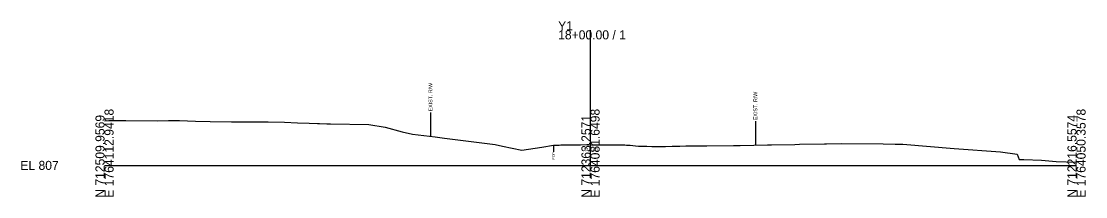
# Model space of a CAD drawing. Extents: x -26 to 1303, y -10 to 9524.
# Drawn here: x -25.7 to 302.8, y 7990.3 to 8044.6 of the extents above; entities that cross this region are included whole.
import ezdxf

# ---------------------------------------------------------------- set-up
doc = ezdxf.new("R2010")
doc.units = 0
for name, color, linetype in [('Default', 7, 'Continuous'), ('Exist Cross Section Cell', 7, 'Continuous'), ('Exist XS Center Line Elevation Label', 7, 'Continuous'), ('Exist XS Ground Line', 7, 'Continuous'), ('Old_Level_10', 7, 'Continuous')]:
    doc.layers.add(name, color=color, linetype=linetype)

msp = doc.modelspace()

# ---------------------------------------------------------------- linework, layer by layer
at = {"layer": 'Exist Cross Section Cell'}
for p, q in [((150, 8000), (150, 8041.75)), ((0, 8000), (150, 8000)), ((150, 8000), (300, 8000))]:
    msp.add_line(p, q, dxfattribs=at)
at = {"layer": 'Exist XS Ground Line'}
msp.add_lwpolyline([(0, 8013.77), (1.29, 8013.85), (2.56, 8013.9), (3.82, 8013.91), (4.25, 8013.89), (5.13, 8013.92), (6.6, 8013.92), (16.38, 8013.8), (19.71, 8013.85), (23.17, 8013.83), (28.09, 8013.65), (32.61, 8013.61), (39.14, 8013.49), (40.34, 8013.48), (42.57, 8013.45), (50.5, 8013.51), (55.51, 8013.38), (59.55, 8013.15), (63.21, 8013), (65.78, 8012.99), (66.33, 8012.97), (68.63, 8012.89), (69.71, 8012.81), (81.61, 8012.65), (86.6, 8011.86), (91.83, 8010.34), (95.03, 8009.69), (102.06, 8008.81), (104.98, 8008.41), (120.54, 8006.42), (122.87, 8005.99), (128.79, 8004.72), (134.95, 8005.63), (138.58, 8006.25), (139.29, 8006.28), (140.33, 8006.3), (140.85, 8006.31), (141.83, 8006.32), (143.6, 8006.33), (144.38, 8006.34), (145.71, 8006.37), (146.94, 8006.38), (148.84, 8006.41), (149.5, 8006.41), (150.35, 8006.39), (151.05, 8006.39), (152.05, 8006.39), (154.14, 8006.37), (154.61, 8006.37), (155.34, 8006.37), (157.16, 8006.36), (158.35, 8006.35), (159.72, 8006.34), (160.59, 8006.31), (161.1, 8006.3), (162.28, 8006.21), (163.9, 8006.06), (164.83, 8005.98), (166.78, 8005.92), (167.39, 8005.91), (168.88, 8005.86), (169.95, 8005.81), (170.99, 8005.82), (172.5, 8005.83), (173.1, 8005.84), (175.2, 8005.91), (175.88, 8005.93), (177.31, 8005.97), (177.61, 8005.98), (179.42, 8006.02), (180.17, 8006.02), (181.52, 8006.04), (182.73, 8006.04), (184.58, 8006.04), (185.28, 8006.04), (185.87, 8006.06), (194.09, 8006.16), (196.17, 8006.14), (204.6, 8006.36), (205.88, 8006.37), (213.02, 8006.49), (214.55, 8006.52), (222.18, 8006.66), (222.8, 8006.66), (227.57, 8006.79), (240.3, 8006.65), (244.01, 8006.57), (246.39, 8006.57), (262.24, 8005.24), (276.56, 8004.14), (281.7, 8003.51), (282.32, 8001.83), (283.7, 8001.78), (289.24, 8001.59), (293.73, 8001.2), (300, 8001.01)], dxfattribs=at)
at = {"layer": 'Old_Level_10'}
for p, q in [((100.6, 8016.4), (100.6, 8009)), ((200.87, 8013.66), (200.87, 8006.26)), ((138.58, 8006.25), (138.58, 8004.2))]:
    msp.add_line(p, q, dxfattribs=at)

# ---------------------------------------------------------------- texts
at = {"layer": 'Default'}
msp.add_text('-', height=0.0001, dxfattribs=at).set_placement((0, 8000))
at = {"layer": 'Exist Cross Section Cell'}
for s, p in [('Y1', (140, 8041.75)), ('18+00.00 / 1', (140, 8038.95)), ('EL 807', (-26, 7998.6))]:
    msp.add_text(s, height=2.8, dxfattribs=at).set_placement(p)
for s, p in [('E 1764112.9418', (2.8, 7990)), ('E 1764081.6498', (152.8, 7990)), ('E 1764050.3578', (302.8, 7990)), ('N 712509.9569', (0, 7990)), ('N 712363.2571', (150, 7990)), ('N 712216.5574', (300, 7990))]:
    msp.add_text(s, height=2.8, rotation=90, dxfattribs=at).set_placement(p)
at = {"layer": 'Exist XS Center Line Elevation Label'}
msp.add_text('813.40', height=1, dxfattribs=at).set_placement((147.97, 8004.4))
at = {"layer": 'Old_Level_10'}
for s, height, p in [('EXIST. R/W', 1.181, (101.19, 8016.7)), ('EXIST. R/W', 1.181, (201.46, 8013.97)), ('EOP', 0.787, (138.97, 8001.8))]:
    msp.add_text(s, height=height, rotation=90, dxfattribs=at).set_placement(p)

doc.saveas('drawing.dxf')
